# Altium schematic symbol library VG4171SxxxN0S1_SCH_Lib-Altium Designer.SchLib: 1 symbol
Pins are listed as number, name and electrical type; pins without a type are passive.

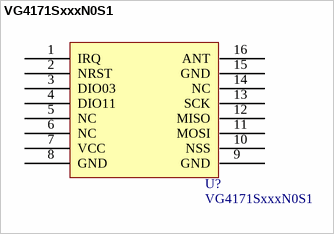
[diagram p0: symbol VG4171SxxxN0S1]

## VG4171SxxxN0S1
designator U?
footprint G238xNS1
footprint G238xNS1_TO
pins: 1 IRQ, 2 NRST, 3 DIO03, 4 DIO11, 5 NC, 6 NC, 7 VCC, 8 GND, 9 GND, 10 NSS, 11 MOSI, 12 MISO, 13 SCK, 14 NC, 15 GND, 16 ANT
